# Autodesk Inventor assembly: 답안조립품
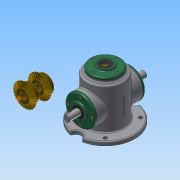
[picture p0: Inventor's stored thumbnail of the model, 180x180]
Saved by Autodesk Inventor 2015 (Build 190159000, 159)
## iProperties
Created: 2018-04
Part Number: 답안조립품
Document SubType Name: Assembly
Designer: user
Author: user
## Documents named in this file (11)
- C:\Users\user\Desktop\480407V1025\답안조립품.iam
- C:\Users\user\Desktop\480407V1025\본체.ipt
- C:\Users\user\Desktop\480407V1025\메인 축.ipt
- 메인 축.ipt
- C:\Users\user\Desktop\480407V1025\커버.ipt
- C:\Users\user\Desktop\480407V1025\오일 실.ipt
- 오일 실.ipt
- C:\Users\user\Desktop\480407V1025\베어링 6203.ipt
- C:\Users\user\Desktop\480407V1025\볼트 M4.ipt
- 볼트 M4.ipt
- C:\Users\user\Desktop\480407V1025\메인 베벨기어.ipt
